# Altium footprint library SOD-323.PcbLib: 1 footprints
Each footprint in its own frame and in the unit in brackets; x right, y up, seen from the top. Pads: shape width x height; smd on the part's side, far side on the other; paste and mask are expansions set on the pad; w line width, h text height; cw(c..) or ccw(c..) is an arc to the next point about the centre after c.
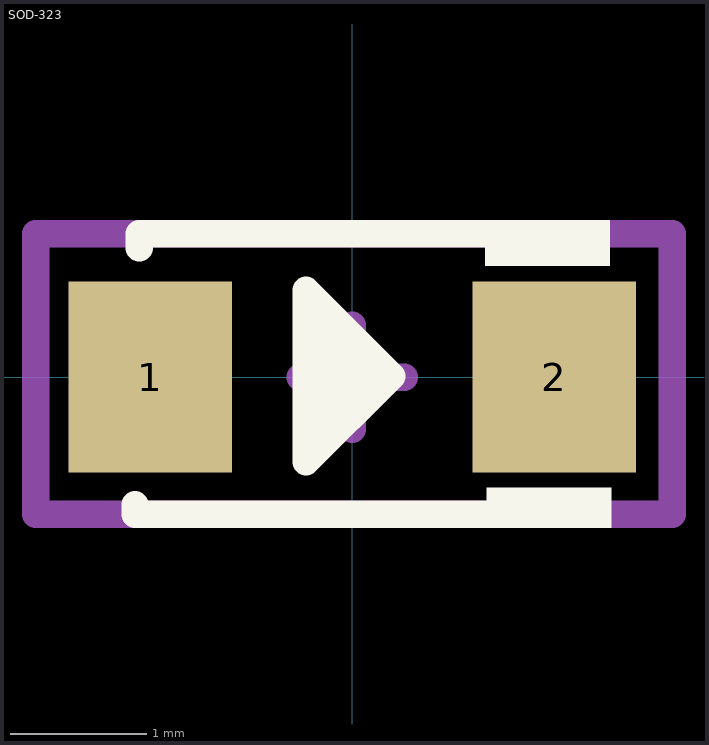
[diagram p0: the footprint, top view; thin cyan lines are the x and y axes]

## SOD-323 [mm] "1.8mm x 1.35mm"
height 1.08
pads (2):
  rect 1.2x1.4 smd: 1(-1.48,0) 2(1.48,0)
Top Overlay:
  rectangle: 0.975,0.815 1.888,1.152
  rectangle: 0.986,-1.105 1.899,-0.81
  region: -0.345,0.674 -0.345,-0.668 0.328,0.005
  lines w0.2: -1.591,-0.932 -1.591,-1.003 1.546,-1.003 ; -1.56,0.946 -1.56,1.05 1.61,1.05 ; -0.339,-0.621 -0.339,0.636 0.29,0.008 -0.339,-0.621
Mechanical 15:
  lines w0.2: -0.381,0 0.381,0 ; 0,-0.381 0,0.381 ; -2.318,-1.003 -2.318,1.051 2.345,1.051 2.345,-1.003 -2.318,-1.003
3D body "User Library-SOD-323.step": height 1.1, standoff 0, extent -1.289,-0.665 1.311,0.685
